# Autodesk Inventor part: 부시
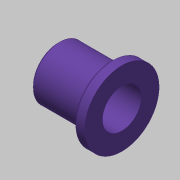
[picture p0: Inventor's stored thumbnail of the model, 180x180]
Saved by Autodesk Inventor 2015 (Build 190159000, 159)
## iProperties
Created: 2019-10
Part Number: 부시
Material: 강철, 연강
Document SubType Name: Modeling
Designer: mduedu
Density: 1 g/cm^3
Appearance: 보라색
Author: mduedu
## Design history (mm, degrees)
sketch "스케치1"
  geometry: L1 (0, 0)-(-18, 0); L2 (0, -5.5)-(0, -10.5); L3 (0, -10.5)-(-3, -10.5); L4 (-3, -10.5)-(-3, -7.5); L5 (-3, -7.5)-(-18, -7.5); L6 (-18, -7.5)-(-18, -5.5); L7 (-18, -5.5)-(0, -5.5)
  constraints: 14 end point, 3 parallel, 2 horizontal, 2 perpendicular, 2 vertical alignment
  dimensions: "d0" = 18 distance of L1.start L1.end; "d1" = 11 diameter of L7 L1; "d2" = 15 diameter of L5 L1; "d3" = 21 diameter of L3 L1; "d4" = 3 distance of L2.end L3.end
revolve "회전1" sketch "스케치1" stored, may be unused: angle "d5" = 90 deg
chamfer "모따기1" distance "d6" = 0.5; stored, may be unused: second distance "d7" = 2, angle "d8" = 45 deg
chamfer "모따기2" distance "d9" = 0.5; stored, may be unused: second distance "d10" = 2, angle "d11" = 45 deg
node "솔리드1"
